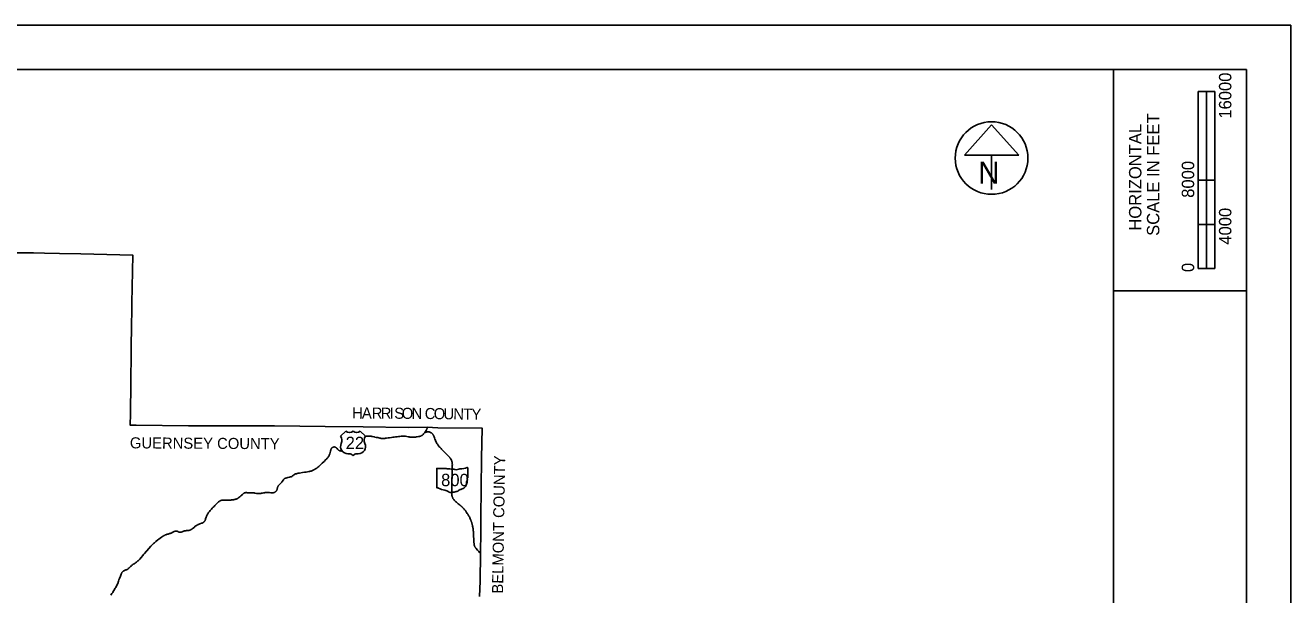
# Model space of a CAD drawing. Extents: x 2125567 to 2397567, y 653347 to 829347.
# Drawn here: x 2283311 to 2397567, y 777872 to 829347 of the extents above; entities that cross this region are included whole.
import ezdxf

# ---------------------------------------------------------------- set-up
doc = ezdxf.new("R2010")
doc.units = 0
for name, color, linetype in [('GM_X_County', 7, 'Continuous'), ('GM_X_County_Text', 7, 'Continuous'), ('GM_X_State_Location', 7, 'Continuous'), ('GM_X_State_Route', 7, 'Continuous'), ('GM_X_State_Shield', 7, 'Continuous'), ('GM_X_US_Location', 7, 'Continuous'), ('GM_X_US_Route', 7, 'Continuous'), ('GM_X_US_Shield', 7, 'Continuous'), ('SH_Border', 7, 'Continuous'), ('SH_Cut_Line', 7, 'Continuous'), ('SH_Data', 7, 'Continuous'), ('SH_Masking', 7, 'Continuous'), ('SH_Text', 7, 'Continuous'), ('UT_P_Electric', 7, 'Continuous')]:
    doc.layers.add(name, color=color, linetype=linetype)

msp = doc.modelspace()

# ---------------------------------------------------------------- linework, layer by layer
at = {"layer": 'GM_X_County'}
msp.add_lwpolyline([(2281956, 808767), (2284041, 808770), (2285053, 808757), (2286394, 808725), (2288328, 808685), (2293016, 808573), (2292939, 804219), (2292926, 803905), (2292919, 803207), (2292907, 802587), (2292795, 794221), (2292778, 793200), (2293328, 793192), (2298034, 793131), (2299170, 793148), (2301762, 793132), (2303151, 793126), (2305817, 793127), (2310373, 793081), (2313829, 793046), (2317868, 792998), (2319608, 793009), (2320574, 792972), (2324571, 792926), (2324488, 790229), (2324467, 787489), (2324446, 784838), (2324439, 782996), (2324423, 782189), (2324401, 781598), (2324369, 779084), (2324336, 777711)], dxfattribs=at)
at = {"layer": 'GM_X_State_Route'}
msp.add_line((2319608, 793009), (2319609, 793021), dxfattribs=at)
for points in [[(2319371, 792533), (2319417, 792598), (2319493, 792706), (2319524, 792755), (2319548, 792795), (2319564, 792828), (2319576, 792855), (2319588, 792889), (2319598, 792927), (2319603, 792957), (2319608, 793009)], [(2324402, 781596), (2324362, 781646), (2324319, 781699), (2324258, 781773), (2324217, 781823), (2324155, 781895), (2324012, 782061), (2323965, 782119), (2323946, 782145), (2323919, 782182), (2323906, 782204), (2323894, 782227), (2323883, 782251), (2323874, 782272), (2323866, 782293), (2323860, 782311), (2323854, 782330), (2323850, 782345), (2323846, 782360), (2323843, 782374), (2323841, 782386), (2323838, 782399), (2323836, 782411), (2323834, 782424), (2323833, 782433), (2323832, 782446), (2323830, 782455), (2323830, 782465), (2323828, 782477), (2323826, 782500), (2323825, 782526), (2323823, 782555), (2323821, 782584), (2323820, 782601), (2323819, 782627), (2323818, 782640), (2323815, 782679), (2323813, 782712), (2323811, 782757), (2323809, 782780), (2323808, 782813), (2323807, 782822), (2323804, 782865), (2323801, 782914), (2323798, 782963), (2323796, 783005), (2323794, 783047), (2323793, 783086), (2323791, 783122), (2323790, 783154), (2323788, 783180), (2323787, 783200), (2323786, 783219), (2323786, 783232), (2323785, 783245), (2323784, 783264), (2323780, 783355), (2323774, 783460), (2323771, 783515), (2323768, 783574), (2323767, 783590), (2323764, 783646), (2323760, 783692), (2323753, 783751), (2323748, 783783), (2323745, 783800), (2323735, 783864), (2323728, 783910), (2323722, 783942), (2323715, 783984), (2323701, 784058), (2323692, 784103), (2323683, 784145), (2323674, 784183), (2323651, 784275), (2323642, 784307), (2323632, 784342), (2323624, 784367), (2323616, 784392), (2323605, 784426), (2323594, 784457), (2323580, 784495), (2323566, 784531), (2323556, 784558), (2323548, 784576), (2323533, 784612), (2323505, 784679), (2323484, 784729), (2323481, 784736), (2323449, 784807), (2323435, 784838), (2323405, 784900), (2323370, 784970), (2323337, 785031), (2323295, 785105), (2323267, 785150), (2323221, 785221), (2323159, 785314), (2323117, 785373), (2323076, 785428), (2323052, 785460), (2323044, 785470), (2323017, 785503), (2322992, 785533), (2322975, 785554), (2322939, 785596), (2322913, 785625), (2322889, 785652), (2322876, 785666), (2322862, 785681), (2322845, 785701), (2322826, 785723), (2322804, 785747), (2322786, 785766), (2322751, 785801), (2322727, 785823), (2322717, 785832), (2322686, 785860), (2322668, 785875), (2322663, 785879), (2322641, 785899), (2322624, 785914), (2322606, 785929), (2322584, 785948), (2322559, 785970), (2322540, 785987), (2322517, 786006), (2322508, 786014), (2322486, 786033), (2322404, 786101), (2322335, 786159), (2322255, 786227), (2322157, 786310), (2322101, 786359), (2322061, 786398), (2322028, 786434), (2321997, 786472), (2321964, 786516), (2321941, 786552), (2321925, 786580), (2321904, 786620), (2321891, 786650), (2321877, 786687), (2321863, 786730), (2321850, 786777), (2321835, 786838), (2321826, 786879), (2321819, 786927), (2321815, 786966), (2321812, 787018), (2321810, 787129), (2321811, 787267), (2321812, 787305), (2321814, 787401), (2321818, 787585), (2321821, 787689), (2321828, 787886), (2321832, 788027), (2321836, 788184), (2321838, 788299), (2321840, 788407), (2321841, 788449), (2321843, 788525), (2321846, 788610), (2321850, 788725), (2321854, 788853), (2321857, 788977), (2321864, 789167), (2321867, 789298), (2321868, 789400), (2321868, 789538), (2321869, 789636), (2321866, 789705), (2321863, 789748), (2321852, 789823), (2321845, 789862), (2321835, 789906), (2321822, 789947), (2321805, 789994), (2321782, 790045), (2321761, 790089), (2321736, 790132), (2321712, 790171), (2321683, 790211), (2321657, 790245), (2321645, 790261), (2321615, 790296), (2321569, 790343), (2321551, 790359), (2321398, 790520), (2321324, 790595), (2321264, 790655), (2321197, 790723), (2321123, 790797), (2321029, 790893), (2320962, 790961), (2320902, 791021), (2320848, 791078), (2320729, 791201), (2320685, 791249), (2320645, 791296), (2320612, 791337), (2320579, 791381), (2320552, 791422), (2320517, 791477), (2320483, 791537), (2320441, 791615), (2320401, 791697), (2320363, 791777), (2320334, 791846), (2320303, 791922), (2320255, 792054), (2320223, 792144), (2320200, 792205), (2320180, 792254), (2320158, 792299), (2320141, 792331), (2320121, 792365), (2320098, 792397), (2320081, 792418), (2320061, 792440), (2320039, 792460), (2320012, 792480), (2319979, 792501), (2319948, 792520), (2319898, 792546), (2319859, 792564), (2319826, 792578), (2319791, 792589), (2319762, 792596), (2319726, 792602), (2319693, 792604), (2319666, 792603), (2319633, 792600), (2319614, 792597), (2319607, 792596), (2319584, 792592), (2319568, 792588), (2319537, 792579), (2319509, 792570), (2319479, 792558), (2319455, 792549), (2319444, 792543), (2319423, 792535), (2319414, 792532), (2319406, 792529), (2319394, 792527), (2319383, 792529), (2319371, 792533)]]:
    msp.add_lwpolyline(points, dxfattribs=at)
at = {"layer": 'GM_X_State_Shield'}
for p, q in [((2320454, 789264), (2320454, 787562)), ((2321302, 789293), (2320482, 789293)), ((2323255, 788445), (2323256, 788445)), ((2323256, 788445), (2323256, 789335))]:
    msp.add_line(p, q, dxfattribs=at)
for centre, major_axis, start_param, end_param in [((2320486, 789267), (32.5, 0), 1.7126934, 3.2834897), ((2321497, 789490), (315, 0), 4.042523, 4.731795), ((2321602, 788338), (1130, 0), 1.4047578, 1.6578581), ((2321858, 789276), (90.8, 0), 3.8360951, 5.1854146), ((2321992, 789079), (189, 0), 0.950623, 2.079405), ((2322235, 789349), (227, 0), 4.0815608, 5.1457227), ((2322637, 788773), (598, 0), 1.6990114, 2.1078141), ((2322258, 791612), (2971, 0), 4.8143942, 5.0423688), ((2323249, 788380), (48.3, 0), 1.8839779, 3.6710726), ((2323225, 789339), (31.2, 0), 6.1411519, 7.9890352), ((2323222, 788442), (33.4, 0), 5.05454, 6.4181714), ((2320486, 787559), (32.7, 0), 3.00124, 4.5083009), ((2320491, 787733), (250, 0), 4.6659457, 4.8974612), ((2320542, 787464), (90.1, 0), 0.5192072, 1.6278991), ((2321680, 788993), (2146, 0), 4.1959971, 4.4889607), ((2321040, 786798), (671, 0), 0.8235189, 1.3235874), ((2322222, 787398), (240, 0), 4.9370686, 5.64225), ((2322737, 787085), (407, 0), 1.6476453, 2.4884337), ((2322424, 787959), (743, 0), 5.1017525, 6.4400178), ((2323367, 788073), (211, 0), 2.3877238, 3.2625369), ((2322941, 788267), (290, 0), 5.9346948, 6.6959481), ((2321766, 787456), (426, 0), 4.0264811, 4.9967352), ((2322013, 786868), (350, 0), 1.495662, 1.9409797), ((2322044, 787328), (227, 0), 4.6910439, 5.5073738), ((2322249, 787164), (63.9, 0), 1.1475842, 2.3151517)]:
    msp.add_ellipse(centre, major_axis=major_axis, ratio=0.8, start_param=start_param, end_param=end_param, dxfattribs=at)
at = {"layer": 'GM_X_US_Route'}
msp.add_line((2319608, 793009), (2319609, 793021), dxfattribs=at)
msp.add_lwpolyline([(2292600, 780226), (2292604, 780229), (2292654, 780271)], dxfattribs=at)
at = {"layer": 'GM_X_US_Shield'}
for p, q in [((2312250, 792667), (2311783, 792200)), ((2314024, 792200), (2313557, 792667)), ((2312437, 790612), (2312530, 790612)), ((2313277, 790612), (2313371, 790612))]:
    msp.add_line(p, q, dxfattribs=at)
for centre, radius, start, end in [((2311247, 791825), 654, 334.54712, 35.00093), ((2312577, 793000), 467, 225.573, 314.427), ((2313231, 793000), 467, 225.573, 314.427), ((2314560, 791825), 654, 144.99907, 205.45288), ((2312429, 791266), 654, 154.83192, 270.63826), ((2313378, 791266), 654, 269.36174, 25.16808), ((2312530, 790145), 467, 36.8699, 90), ((2313277, 790145), 467, 90, 143.1301)]:
    msp.add_arc(centre, radius, start, end, dxfattribs=at)
at = {"layer": 'SH_Border'}
for p, q in [((2381567, 657347), (2381567, 825347)), ((2381567, 805347), (2393567, 805347))]:
    msp.add_line(p, q, dxfattribs=at)
msp.add_lwpolyline([(2137567, 825347), (2393567, 825347), (2393567, 657347), (2137567, 657347)], close=True, dxfattribs=at)
at = {"layer": 'SH_Cut_Line'}
msp.add_lwpolyline([(2125567, 653347), (2397567, 653347), (2397567, 829347), (2125567, 829347)], close=True, dxfattribs=at)
at = {"layer": 'SH_Data'}
for p, q in [((2389220, 807347), (2389220, 823347)), ((2390720, 823347), (2389220, 823347)), ((2389220, 815347), (2389220, 823347)), ((2389220, 823347), (2389967, 823347)), ((2389967, 823347), (2389974, 823347)), ((2389974, 823347), (2389974, 815347)), ((2390720, 823347), (2390720, 807347)), ((2389974, 815347), (2389220, 815347)), ((2390714, 815347), (2389967, 815347)), ((2389967, 815347), (2389967, 811347)), ((2390714, 811347), (2390714, 815347)), ((2389967, 811347), (2389220, 811347)), ((2389220, 811347), (2389220, 807347)), ((2389967, 807347), (2389967, 811347)), ((2389967, 811347), (2390714, 811347)), ((2390720, 807347), (2389220, 807347)), ((2389220, 807347), (2389967, 807347))]:
    msp.add_line(p, q, dxfattribs=at)
at = {"layer": 'SH_Masking'}
msp.add_circle((2370559, 817345), 3280, dxfattribs=at)
at = {"layer": 'SH_Text'}
for p, q in [((2370559, 820335), (2368099, 817605)), ((2373020, 817605), (2370559, 820335)), ((2368099, 817605), (2373020, 817605)), ((2370559, 817605), (2370559, 814511))]:
    msp.add_line(p, q, dxfattribs=at)
msp.add_circle((2370559, 817345), 3280, dxfattribs=at)
at = {"layer": 'UT_P_Electric'}
for points in [[(2319371, 792533), (2319417, 792598), (2319493, 792706), (2319524, 792755), (2319548, 792795), (2319564, 792828), (2319576, 792855), (2319588, 792889), (2319598, 792927), (2319603, 792957), (2319608, 793009)], [(2314006, 792173), (2314018, 792177), (2314050, 792187), (2314085, 792195), (2314125, 792202), (2314161, 792206), (2314203, 792209), (2314279, 792210), (2314355, 792209), (2314414, 792206), (2314479, 792201), (2314548, 792192), (2314603, 792184), (2314667, 792171), (2314776, 792148), (2314850, 792132), (2314869, 792128), (2315000, 792098), (2315090, 792078), (2315135, 792069), (2315315, 792028), (2315379, 792015), (2315434, 792005), (2315486, 791998), (2315538, 791994), (2315577, 791993), (2315613, 791993), (2315672, 791996), (2315760, 792004), (2315828, 792012), (2315935, 792026), (2316075, 792045), (2316202, 792061), (2316368, 792083), (2316491, 792099), (2316608, 792114), (2316751, 792134), (2316888, 792151), (2317021, 792169), (2317122, 792182), (2317252, 792198), (2317324, 792206), (2317383, 792211), (2317426, 792212), (2317469, 792212), (2317515, 792209), (2317567, 792204), (2317632, 792194), (2317762, 792170), (2317903, 792143), (2317984, 792130), (2318039, 792123), (2318104, 792116), (2318166, 792112), (2318229, 792110), (2318297, 792110), (2318366, 792112), (2318450, 792118), (2318548, 792126), (2318639, 792136), (2318708, 792145), (2318805, 792160), (2318862, 792171), (2318914, 792183), (2318961, 792195), (2318995, 792207), (2319025, 792218), (2319061, 792235), (2319098, 792255), (2319131, 792276), (2319135, 792279)], [(2319135, 792279), (2319163, 792299), (2319193, 792323), (2319205, 792334), (2319242, 792366), (2319278, 792403), (2319300, 792433), (2319322, 792465), (2319371, 792533)], [(2306061, 787475), (2306068, 787513), (2306076, 787548), (2306088, 787586), (2306102, 787623), (2306116, 787653), (2306132, 787681), (2306150, 787709), (2306170, 787736), (2306194, 787763), (2306226, 787796), (2306290, 787858), (2306323, 787889), (2306385, 787949), (2306411, 787977), (2306439, 788009), (2306466, 788046), (2306505, 788102), (2306609, 788261), (2306634, 788295), (2306654, 788318), (2306672, 788337), (2306692, 788354), (2306714, 788370), (2306739, 788385), (2306766, 788399), (2306797, 788411), (2306832, 788421), (2306914, 788443), (2307020, 788466), (2307139, 788493), (2307176, 788501), (2307262, 788522), (2307293, 788531), (2307326, 788543), (2307364, 788561), (2307403, 788585), (2307443, 788613), (2307491, 788652), (2307557, 788706), (2307603, 788738), (2307628, 788753), (2307655, 788767), (2307703, 788787), (2307744, 788800), (2307791, 788814), (2307865, 788830), (2307945, 788846), (2308055, 788865), (2308346, 788912), (2308533, 788941), (2308663, 788962), (2308798, 788985), (2308898, 789002), (2308969, 789015), (2309039, 789032), (2309108, 789051), (2309173, 789073), (2309232, 789095), (2309292, 789120), (2309351, 789147), (2309404, 789174), (2309464, 789207), (2309514, 789238), (2309568, 789275), (2309619, 789311), (2309672, 789354), (2309734, 789407), (2309801, 789470), (2309809, 789477), (2309932, 789594), (2310120, 789772), (2310285, 789927), (2310448, 790080), (2310516, 790147), (2310564, 790196), (2310608, 790244), (2310628, 790270), (2310663, 790317), (2310693, 790364), (2310715, 790403), (2310737, 790447), (2310757, 790492), (2310779, 790550), (2310801, 790618), (2310829, 790716), (2310862, 790846), (2310874, 790892), (2310887, 790945), (2310901, 790989), (2310914, 791023), (2310928, 791053), (2310945, 791082), (2310962, 791107), (2310978, 791127), (2310997, 791147), (2311017, 791164), (2311039, 791180), (2311066, 791197), (2311102, 791212), (2311132, 791220), (2311158, 791225), (2311185, 791228), (2311211, 791227), (2311238, 791225), (2311264, 791220), (2311290, 791213), (2311314, 791203), (2311338, 791191), (2311358, 791179), (2311380, 791164), (2311405, 791142), (2311430, 791116), (2311465, 791077), (2311513, 791019), (2311541, 790988), (2311567, 790963), (2311589, 790944), (2311613, 790927), (2311637, 790912), (2311663, 790898), (2311690, 790887), (2311721, 790877), (2311752, 790869), (2311781, 790865), (2311810, 790863), (2311838, 790863), (2311867, 790866), (2311896, 790871), (2311906, 790874)], [(2292654, 780271), (2292756, 780371), (2292803, 780417), (2292856, 780466), (2292911, 780513), (2292955, 780548), (2293000, 780581), (2293059, 780622), (2293142, 780675), (2293228, 780730), (2293268, 780757), (2293303, 780782), (2293362, 780828), (2293417, 780874), (2293473, 780925), (2293529, 780979), (2293584, 781036), (2293641, 781099), (2293768, 781245), (2293913, 781414), (2293989, 781500), (2294068, 781588), (2294459, 782043), (2294658, 782268), (2294710, 782323), (2294754, 782367), (2294845, 782459), (2294885, 782497), (2294962, 782570), (2294998, 782603), (2295060, 782657), (2295109, 782696), (2295281, 782828), (2295376, 782898), (2295612, 783066), (2295696, 783127), (2295758, 783170), (2295822, 783212), (2295867, 783239), (2295910, 783262), (2295946, 783279), (2295992, 783298), (2296045, 783317), (2296098, 783333), (2296200, 783360), (2296323, 783393), (2296395, 783415), (2296441, 783430), (2296483, 783447), (2296528, 783467), (2296574, 783491), (2296619, 783517), (2296695, 783563), (2296739, 783586), (2296772, 783601), (2296800, 783611), (2296829, 783618), (2296858, 783624), (2296901, 783629), (2296931, 783630), (2296957, 783629), (2296977, 783626), (2296997, 783621), (2297015, 783614), (2297032, 783607), (2297068, 783591), (2297101, 783577), (2297128, 783565), (2297155, 783553), (2297185, 783541), (2297202, 783535), (2297220, 783530), (2297239, 783527), (2297271, 783523), (2297287, 783521), (2297312, 783521), (2297341, 783524), (2297365, 783526), (2297393, 783531), (2297413, 783537), (2297430, 783542), (2297448, 783549), (2297489, 783565), (2297594, 783611), (2297611, 783616), (2297629, 783622), (2297679, 783634), (2297724, 783645), (2297771, 783654), (2297794, 783657), (2297817, 783659), (2297877, 783662), (2297920, 783663), (2297982, 783666), (2298003, 783666), (2298025, 783669), (2298045, 783672), (2298065, 783676), (2298106, 783687), (2298131, 783695), (2298157, 783704), (2298196, 783719), (2298226, 783732), (2298243, 783741), (2298270, 783754), (2298287, 783763), (2298336, 783791), (2298354, 783802), (2298371, 783813), (2298387, 783826), (2298412, 783846), (2298430, 783860), (2298472, 783896), (2298574, 783988), (2298616, 784024), (2298661, 784059), (2298716, 784099), (2298769, 784133), (2298819, 784164), (2298868, 784191), (2298900, 784207), (2298945, 784228), (2299000, 784250), (2299062, 784273), (2299223, 784329), (2299281, 784352), (2299328, 784373), (2299366, 784393), (2299382, 784403), (2299411, 784424), (2299436, 784445), (2299459, 784467), (2299481, 784492), (2299502, 784520), (2299521, 784551), (2299540, 784585), (2299557, 784623), (2299575, 784669), (2299596, 784731), (2299642, 784875), (2299662, 784934), (2299680, 784980), (2299704, 785038), (2299729, 785091), (2299755, 785141), (2299789, 785197), (2299825, 785252), (2299860, 785300), (2299900, 785352), (2299947, 785407), (2300016, 785486), (2300116, 785594), (2300197, 785684), (2300226, 785716), (2300285, 785782), (2300349, 785851), (2300355, 785857), (2300420, 785929), (2300436, 785946), (2300475, 785990), (2300512, 786031), (2300622, 786153), (2300658, 786191), (2300689, 786221), (2300722, 786249), (2300758, 786276), (2300802, 786307), (2300841, 786331), (2300878, 786352), (2300911, 786367), (2300951, 786383), (2300995, 786397), (2301036, 786408), (2301081, 786418), (2301127, 786425), (2301170, 786429), (2301216, 786432), (2301252, 786433), (2301324, 786432), (2301409, 786431), (2301521, 786429), (2301594, 786428), (2301721, 786427), (2301806, 786429), (2301874, 786432), (2301940, 786438), (2302008, 786446), (2302095, 786459), (2302176, 786473), (2302240, 786486), (2302300, 786502), (2302356, 786518), (2302396, 786532), (2302432, 786547), (2302461, 786561), (2302490, 786578), (2302519, 786597), (2302545, 786617), (2302601, 786663), (2302670, 786723), (2302769, 786810), (2302774, 786814), (2302850, 786881), (2302857, 786888), (2302923, 786946), (2302970, 786987), (2303023, 787032), (2303047, 787049), (2303058, 787057), (2303073, 787065), (2303083, 787071), (2303096, 787077), (2303105, 787081), (2303115, 787084), (2303125, 787087), (2303138, 787090), (2303149, 787092), (2303164, 787094), (2303182, 787095), (2303207, 787097), (2303256, 787098), (2303289, 787097), (2303341, 787096), (2303472, 787092), (2303555, 787090), (2303803, 787084), (2303809, 787083), (2303888, 787081), (2303937, 787077), (2303990, 787070), (2304041, 787060), (2304172, 787031), (2304230, 787020), (2304282, 787012), (2304327, 787008), (2304369, 787007), (2304415, 787008), (2304467, 787011), (2304519, 787017), (2304570, 787025), (2304635, 787038), (2304728, 787058), (2304847, 787083), (2304902, 787093), (2304964, 787101), (2305019, 787107), (2305075, 787110), (2305131, 787111), (2305216, 787108), (2305347, 787102), (2305495, 787094), (2305593, 787090), (2305645, 787089), (2305684, 787091), (2305723, 787096), (2305748, 787101), (2305773, 787107), (2305801, 787117), (2305827, 787128), (2305853, 787142), (2305880, 787160), (2305906, 787179), (2305928, 787198), (2305948, 787219), (2305969, 787244), (2305989, 787274), (2306006, 787302), (2306020, 787330), (2306033, 787360), (2306042, 787388), (2306050, 787419), (2306059, 787464), (2306061, 787475)], [(2291037, 777821), (2291135, 777976), (2291170, 778031), (2291200, 778078), (2291254, 778165), (2291318, 778264), (2291435, 778453), (2291483, 778535), (2291524, 778613), (2291566, 778699), (2291609, 778794), (2291651, 778897), (2291723, 779086), (2291770, 779214), (2291814, 779326), (2291895, 779534), (2291966, 779728), (2291992, 779788), (2292002, 779810), (2292009, 779824), (2292019, 779843), (2292027, 779858), (2292038, 779876), (2292066, 779914), (2292083, 779934), (2292097, 779948), (2292115, 779965), (2292131, 779979), (2292147, 779992), (2292165, 780006), (2292186, 780019), (2292208, 780032), (2292234, 780045), (2292258, 780056), (2292324, 780080), (2292400, 780109), (2292453, 780134), (2292504, 780162), (2292554, 780194), (2292600, 780226)]]:
    msp.add_lwpolyline(points, dxfattribs=at)

# ---------------------------------------------------------------- texts
at = {"layer": 'GM_X_County_Text'}
for s, rotation, p in [('H', 359.59331, (2312814, 793806)), ('A', 359.5946, (2313699, 793799)), ('R', 359.59358, (2314583, 793793)), ('R', 359.59358, (2315397, 793787)), ('I', 359.59342, (2316211, 793782)), ('S', 359.59267, (2316620, 793779)), ('O', 359.59222, (2317298, 793774)), ('N', 359.53568, (2318182, 793768)), ('C', 359.31238, (2319369, 793757)), ('O', 359.1344, (2320182, 793748)), ('U', 359.0822, (2321066, 793734)), ('N', 359.08002, (2321950, 793720)), ('T', 359.07942, (2322835, 793706)), ('Y', 359.07997, (2323583, 793694)), ('GUERNSEY COUNTY', 359.64169, (2292750, 791104)), ('BELMONT COUNTY', 89.06707, (2326444, 777969))]:
    msp.add_text(s, height=1000, rotation=rotation, dxfattribs=at).set_placement(p)
at = {"layer": 'GM_X_State_Location'}
msp.add_text('800', height=1, rotation=0.00001, dxfattribs=at).set_placement((2321483, 787993))
for s in ['s', 'r']:
    msp.add_text(s, height=1, dxfattribs=at).set_placement((2321836, 788066))
at = {"layer": 'GM_X_State_Shield'}
msp.add_text('800', height=1120.7, dxfattribs=at).set_placement((2320853, 787682))
at = {"layer": 'GM_X_US_Location'}
for p in [(2312846, 791333), (2298432, 783655)]:
    msp.add_text('22', height=1, rotation=0.00001, dxfattribs=at).set_placement(p)
for s, p in [('0', (2313053, 791540)), ('/', (2313053, 791540)), ('0', (2298638, 783862)), ('/', (2298638, 783862))]:
    msp.add_text(s, height=1, dxfattribs=at).set_placement(p)
at = {"layer": 'GM_X_US_Shield'}
msp.add_text('22', height=1120.7, dxfattribs=at).set_placement((2312234, 791032))
at = {"layer": 'SH_Data'}
for s, p in [('16000', (2392210, 820905)), ('HORIZONTAL', (2384087, 810780)), ('SCALE IN FEET', (2385707, 810311)), ('8000', (2388851, 813752)), ('4000', (2392210, 809514)), ('0', (2388851, 807037))]:
    msp.add_text(s, height=1120, rotation=90, dxfattribs=at).set_placement(p)
at = {"layer": 'SH_Text'}
msp.add_text('N', height=2000, dxfattribs=at).set_placement((2369349, 815015))

doc.saveas('drawing.dxf')
